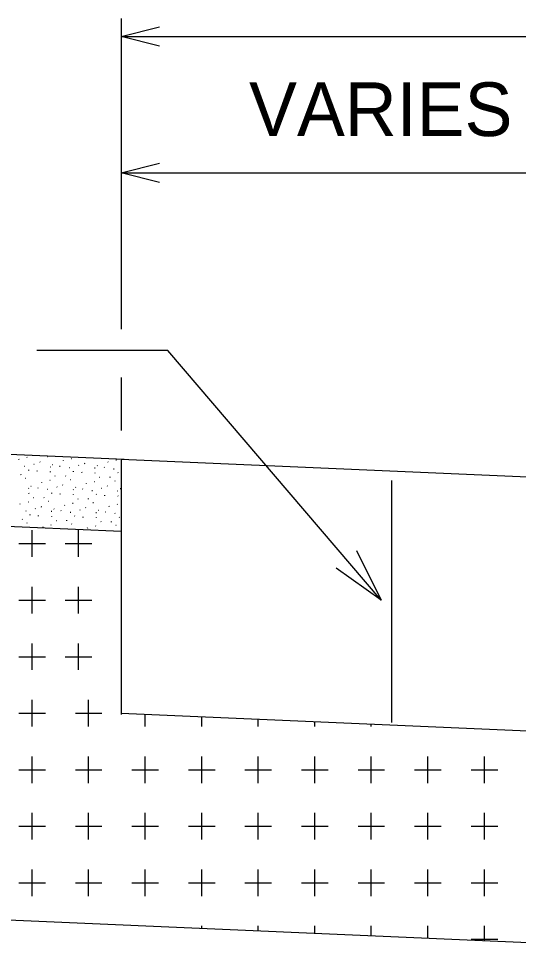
# Model space of a CAD drawing. Extents: x 0 to 34, y 0 to 22.
# Drawn here: x 21.318 to 22.622, y 3.808 to 6.233 of the extents above; entities that cross this region are included whole.
import ezdxf

# ---------------------------------------------------------------- set-up
doc = ezdxf.new("R2010")
doc.units = 0
doc.layers.add('TX_P_1', color=7, linetype='Continuous')

msp = doc.modelspace()

# ---------------------------------------------------------------- linework, layer by layer
at = {"layer": 'TX_P_1'}
for p, q in [((21.5858, 6.2331), (21.5858, 5.779)), ((21.5858, 6.1866), (23.7143, 6.1866)), ((21.5858, 5.8772), (21.5858, 5.4231)), ((21.5858, 5.8307), (23.0049, 5.8307)), ((21.7073, 5.3674), (21.3658, 5.3674)), ((22.2639, 4.7164), (21.7073, 5.3674)), ((21.5858, 5.2971), (21.5858, 5.1591)), ((21.3196, 5.0826), (21.3189, 5.0839)), ((21.3396, 5.0889), (21.3408, 5.0887)), ((21.3581, 5.0712), (21.3593, 5.0711)), ((21.3733, 5.0771), (21.3744, 5.0761)), ((21.3928, 5.0909), (21.3939, 5.0907)), ((21.4066, 5.0702), (21.4078, 5.0701)), ((21.4358, 5.0792), (21.4353, 5.0806)), ((21.4559, 5.0857), (21.4569, 5.0856)), ((21.4896, 5.0737), (21.4908, 5.0729)), ((21.5519, 5.0759), (21.5514, 5.0772)), ((21.5721, 5.0824), (21.5733, 5.0822)), ((21.5858, 5.0816), (21.5858, 4.4181)), ((21.3336, 5.0656), (21.3346, 5.0654)), ((21.3454, 5.0544), (21.3449, 5.0559)), ((21.3674, 5.0517), (21.3669, 5.0532)), ((21.4004, 5.0644), (21.4014, 5.0642)), ((21.4019, 5.0504), (21.4014, 5.0517)), ((21.4251, 5.0661), (21.4263, 5.0659)), ((21.4499, 5.0624), (21.4509, 5.0621)), ((21.4618, 5.0512), (21.4613, 5.0526)), ((21.4744, 5.0679), (21.4754, 5.0677)), ((21.4838, 5.0486), (21.4833, 5.0499)), ((21.5166, 5.0612), (21.5178, 5.0611)), ((21.5183, 5.0471), (21.5178, 5.0486)), ((21.5229, 5.0671), (21.5241, 5.0667)), ((21.5414, 5.0629), (21.5424, 5.0626)), ((21.5661, 5.0591), (21.5673, 5.0589)), ((21.5779, 5.0479), (21.5774, 5.0494)), ((21.3249, 5.0426), (21.3244, 5.0441)), ((21.3363, 5.0344), (21.3374, 5.0341)), ((21.3793, 5.0227), (21.3788, 5.0241)), ((21.3994, 5.0292), (21.4004, 5.0291)), ((21.4131, 5.0406), (21.4141, 5.0404)), ((21.4411, 5.0394), (21.4406, 5.0407)), ((21.4526, 5.0311), (21.4536, 5.0309)), ((21.4956, 5.0194), (21.4951, 5.0209)), ((21.5156, 5.0259), (21.5166, 5.0257)), ((21.5293, 5.0374), (21.5304, 5.0371)), ((21.5574, 5.0361), (21.5569, 5.0376)), ((21.5689, 5.0279), (21.5699, 5.0276)), ((22.2908, 5.0282), (22.2908, 4.4079)), ((21.3439, 5.0081), (21.3449, 5.0077)), ((21.3503, 5.0137), (21.3513, 5.0136)), ((21.3686, 5.0096), (21.3696, 5.0094)), ((21.3934, 5.0057), (21.3944, 5.0056)), ((21.4051, 4.9947), (21.4046, 4.9961)), ((21.4179, 5.0116), (21.4189, 5.0112)), ((21.4331, 5.0172), (21.4341, 5.0164)), ((21.4603, 5.0047), (21.4613, 5.0044)), ((21.4664, 5.0106), (21.4676, 5.0104)), ((21.4849, 5.0062), (21.4859, 5.0061)), ((21.5096, 5.0026), (21.5106, 5.0024)), ((21.5341, 5.0082), (21.5353, 5.0081)), ((21.5494, 5.0141), (21.5504, 5.0132)), ((21.5764, 5.0014), (21.5774, 5.0012)), ((21.5828, 5.0072), (21.5838, 5.0071)), ((21.3429, 4.9727), (21.3439, 4.9726)), ((21.3456, 4.9939), (21.3451, 4.9952)), ((21.3566, 4.9841), (21.3576, 4.9839)), ((21.3848, 4.9829), (21.3843, 4.9842)), ((21.3961, 4.9746), (21.3971, 4.9744)), ((21.4273, 4.9921), (21.4266, 4.9934)), ((21.4618, 4.9906), (21.4613, 4.9919)), ((21.4728, 4.9809), (21.4739, 4.9807)), ((21.5009, 4.9797), (21.5004, 4.9811)), ((21.5214, 4.9914), (21.5209, 4.9927)), ((21.5434, 4.9887), (21.5429, 4.9902)), ((21.5781, 4.9874), (21.5774, 4.9887)), ((21.3228, 4.9662), (21.3223, 4.9676)), ((21.3368, 4.9494), (21.3379, 4.9491)), ((21.3614, 4.9549), (21.3624, 4.9547)), ((21.3766, 4.9607), (21.3778, 4.9599)), ((21.4036, 4.9482), (21.4048, 4.9481)), ((21.4099, 4.9541), (21.4111, 4.9537)), ((21.4284, 4.9499), (21.4294, 4.9496)), ((21.4391, 4.9629), (21.4384, 4.9644)), ((21.4591, 4.9694), (21.4603, 4.9692)), ((21.4776, 4.9517), (21.4786, 4.9516)), ((21.4929, 4.9576), (21.4939, 4.9567)), ((21.5123, 4.9712), (21.5134, 4.9711)), ((21.5263, 4.9507), (21.5273, 4.9506)), ((21.5553, 4.9597), (21.5548, 4.9611)), ((21.5754, 4.9662), (21.5764, 4.9659)), ((21.3283, 4.9264), (21.3276, 4.9277)), ((21.3488, 4.9382), (21.3483, 4.9396)), ((21.3706, 4.9356), (21.3701, 4.9369)), ((21.4053, 4.9341), (21.4048, 4.9356)), ((21.4164, 4.9244), (21.4174, 4.9241)), ((21.4444, 4.9231), (21.4439, 4.9246)), ((21.4531, 4.9461), (21.4543, 4.9459)), ((21.4649, 4.9349), (21.4644, 4.9364)), ((21.4869, 4.9322), (21.4864, 4.9336)), ((21.5199, 4.9449), (21.5211, 4.9447)), ((21.5216, 4.9307), (21.5211, 4.9322)), ((21.5446, 4.9466), (21.5458, 4.9464)), ((21.5694, 4.9429), (21.5704, 4.9426)), ((21.5813, 4.9316), (21.5806, 4.9331)), ((21.3396, 4.9181), (21.3408, 4.9179)), ((21.3826, 4.9066), (21.3821, 4.9079)), ((21.4026, 4.9129), (21.4036, 4.9127)), ((21.4559, 4.9149), (21.4569, 4.9146)), ((21.4988, 4.9032), (21.4983, 4.9046)), ((21.5188, 4.9097), (21.5199, 4.9096)), ((21.5326, 4.9211), (21.5336, 4.9209)), ((21.5608, 4.9199), (21.5603, 4.9212)), ((21.5721, 4.9116), (21.5731, 4.9114)), ((21.3536, 4.8289), (21.3536, 4.8984)), ((21.4743, 4.8637), (21.4743, 4.8984)), ((21.5526, 4.8977), (21.5528, 4.8976)), ((21.3188, 4.8637), (21.3883, 4.8637)), ((21.4394, 4.8637), (21.4743, 4.8637)), ((21.4743, 4.8289), (21.4743, 4.8637)), ((21.4743, 4.8637), (21.5089, 4.8637)), ((21.3536, 4.7162), (21.3536, 4.7509)), ((21.4743, 4.6814), (21.4743, 4.7509)), ((21.3188, 4.7162), (21.3536, 4.7162)), ((21.3536, 4.6814), (21.3536, 4.7162)), ((21.3536, 4.7162), (21.3883, 4.7162)), ((21.4394, 4.7162), (21.5089, 4.7162)), ((21.3536, 4.5341), (21.3536, 4.6036)), ((21.4743, 4.5687), (21.4743, 4.6036)), ((21.3188, 4.5687), (21.3883, 4.5687)), ((21.4394, 4.5687), (21.4743, 4.5687)), ((21.4743, 4.5341), (21.4743, 4.5687)), ((21.4743, 4.5687), (21.5089, 4.5687)), ((21.3536, 4.4214), (21.3536, 4.4561)), ((21.5009, 4.3866), (21.5009, 4.4561)), ((21.3188, 4.4214), (21.3536, 4.4214)), ((21.3536, 4.3866), (21.3536, 4.4214)), ((21.3536, 4.4214), (21.3883, 4.4214)), ((21.4663, 4.4214), (21.5358, 4.4214)), ((21.6484, 4.3866), (21.6484, 4.4187)), ((21.7958, 4.3866), (21.7958, 4.4122)), ((21.9433, 4.3866), (21.9433, 4.4059)), ((22.0906, 4.3866), (22.0906, 4.3996)), ((22.2379, 4.3866), (22.2379, 4.3931)), ((22.2908, 4.4079), (22.2908, 4.3969)), ((22.3854, 4.3866), (22.3854, 4.3867)), ((21.3536, 4.2392), (21.3536, 4.3087)), ((21.5009, 4.2739), (21.5009, 4.3087)), ((21.6484, 4.2392), (21.6484, 4.3087)), ((21.7958, 4.2739), (21.7958, 4.3087)), ((21.9433, 4.2392), (21.9433, 4.3087)), ((22.0906, 4.2739), (22.0906, 4.3087)), ((22.2379, 4.2392), (22.2379, 4.3087)), ((22.3854, 4.2739), (22.3854, 4.3087)), ((22.5329, 4.2392), (22.5329, 4.3087)), ((21.3188, 4.2739), (21.3883, 4.2739)), ((21.4663, 4.2739), (21.5009, 4.2739)), ((21.5009, 4.2392), (21.5009, 4.2739)), ((21.5009, 4.2739), (21.5358, 4.2739)), ((21.6136, 4.2739), (21.6831, 4.2739)), ((21.7611, 4.2739), (21.7958, 4.2739)), ((21.7958, 4.2392), (21.7958, 4.2739)), ((21.7958, 4.2739), (21.8306, 4.2739)), ((21.9084, 4.2739), (21.9779, 4.2739)), ((22.0558, 4.2739), (22.0906, 4.2739)), ((22.0906, 4.2392), (22.0906, 4.2739)), ((22.0906, 4.2739), (22.1253, 4.2739)), ((22.2033, 4.2739), (22.2728, 4.2739)), ((22.3508, 4.2739), (22.3854, 4.2739)), ((22.3854, 4.2392), (22.3854, 4.2739)), ((22.3854, 4.2739), (22.4201, 4.2739)), ((22.4981, 4.2739), (22.5676, 4.2739)), ((21.3536, 4.1266), (21.3536, 4.1614)), ((21.5009, 4.0919), (21.5009, 4.1614)), ((21.6484, 4.1266), (21.6484, 4.1614)), ((21.7958, 4.0919), (21.7958, 4.1614)), ((21.9433, 4.1266), (21.9433, 4.1614)), ((22.0906, 4.0919), (22.0906, 4.1614)), ((22.2379, 4.1266), (22.2379, 4.1614)), ((22.3854, 4.0919), (22.3854, 4.1614)), ((22.5329, 4.1266), (22.5329, 4.1614)), ((21.3188, 4.1266), (21.3536, 4.1266)), ((21.3536, 4.0919), (21.3536, 4.1266)), ((21.3536, 4.1266), (21.3883, 4.1266)), ((21.4663, 4.1266), (21.5358, 4.1266)), ((21.6136, 4.1266), (21.6484, 4.1266)), ((21.6484, 4.0919), (21.6484, 4.1266)), ((21.6484, 4.1266), (21.6831, 4.1266)), ((21.7611, 4.1266), (21.8306, 4.1266)), ((21.9084, 4.1266), (21.9433, 4.1266)), ((21.9433, 4.0919), (21.9433, 4.1266)), ((21.9433, 4.1266), (21.9779, 4.1266)), ((22.0558, 4.1266), (22.1253, 4.1266)), ((22.2033, 4.1266), (22.2379, 4.1266)), ((22.2379, 4.0919), (22.2379, 4.1266)), ((22.2379, 4.1266), (22.2728, 4.1266)), ((22.3508, 4.1266), (22.4201, 4.1266)), ((22.4981, 4.1266), (22.5329, 4.1266)), ((22.5329, 4.0919), (22.5329, 4.1266)), ((22.5329, 4.1266), (22.5676, 4.1266)), ((21.3536, 3.9444), (21.3536, 4.0139)), ((21.5009, 3.9792), (21.5009, 4.0139)), ((21.6484, 3.9444), (21.6484, 4.0139)), ((21.7958, 3.9792), (21.7958, 4.0139)), ((21.9433, 3.9444), (21.9433, 4.0139)), ((22.0906, 3.9792), (22.0906, 4.0139)), ((22.2379, 3.9444), (22.2379, 4.0139)), ((22.3854, 3.9792), (22.3854, 4.0139)), ((22.5329, 3.9444), (22.5329, 4.0139)), ((21.3188, 3.9792), (21.3883, 3.9792)), ((21.4663, 3.9792), (21.5009, 3.9792)), ((21.5009, 3.9444), (21.5009, 3.9792)), ((21.5009, 3.9792), (21.5358, 3.9792)), ((21.6136, 3.9792), (21.6831, 3.9792)), ((21.7611, 3.9792), (21.7958, 3.9792)), ((21.7958, 3.9444), (21.7958, 3.9792)), ((21.7958, 3.9792), (21.8306, 3.9792)), ((21.9084, 3.9792), (21.9779, 3.9792)), ((22.0558, 3.9792), (22.0906, 3.9792)), ((22.0906, 3.9444), (22.0906, 3.9792)), ((22.0906, 3.9792), (22.1253, 3.9792)), ((22.2033, 3.9792), (22.2728, 3.9792)), ((22.3508, 3.9792), (22.3854, 3.9792)), ((22.3854, 3.9444), (22.3854, 3.9792)), ((22.3854, 3.9792), (22.4201, 3.9792)), ((22.4981, 3.9792), (22.5676, 3.9792)), ((21.7958, 3.8606), (21.7958, 3.8666)), ((21.9433, 3.8541), (21.9433, 3.8666)), ((22.0906, 3.8477), (22.0906, 3.8666)), ((22.2379, 3.8414), (22.2379, 3.8666)), ((22.3854, 3.8349), (22.3854, 3.8666)), ((22.5329, 3.8317), (22.5329, 3.8666)), ((22.4981, 3.8317), (22.5329, 3.8317)), ((22.5329, 3.8286), (22.5329, 3.8317)), ((22.5329, 3.8317), (22.5676, 3.8317))]:
    msp.add_line(p, q, dxfattribs=at)
for points in [[(21.6861, 6.1616), (21.5858, 6.1866), (21.6861, 6.2118)], [(21.6861, 5.8057), (21.5858, 5.8307), (21.6861, 5.8559)], [(20.6324, 5.1254), (21.5936, 5.0837)], [(21.5858, 5.0841), (22.9864, 5.0234), (23.7144, 4.9312)], [(20.6324, 4.9376), (21.5861, 4.8962)], [(22.1996, 4.8455), (22.2639, 4.7164), (22.1464, 4.8001)], [(21.5859, 4.4214), (22.9864, 4.3607)], [(20.6324, 3.9109), (22.9864, 3.8089), (22.9939, 3.8079)]]:
    msp.add_lwpolyline(points, dxfattribs=at)

# ---------------------------------------------------------------- texts
msp.add_text('VARIES', height=0.14, dxfattribs=at).set_placement((21.9193, 5.9267))

doc.saveas('drawing.dxf')
